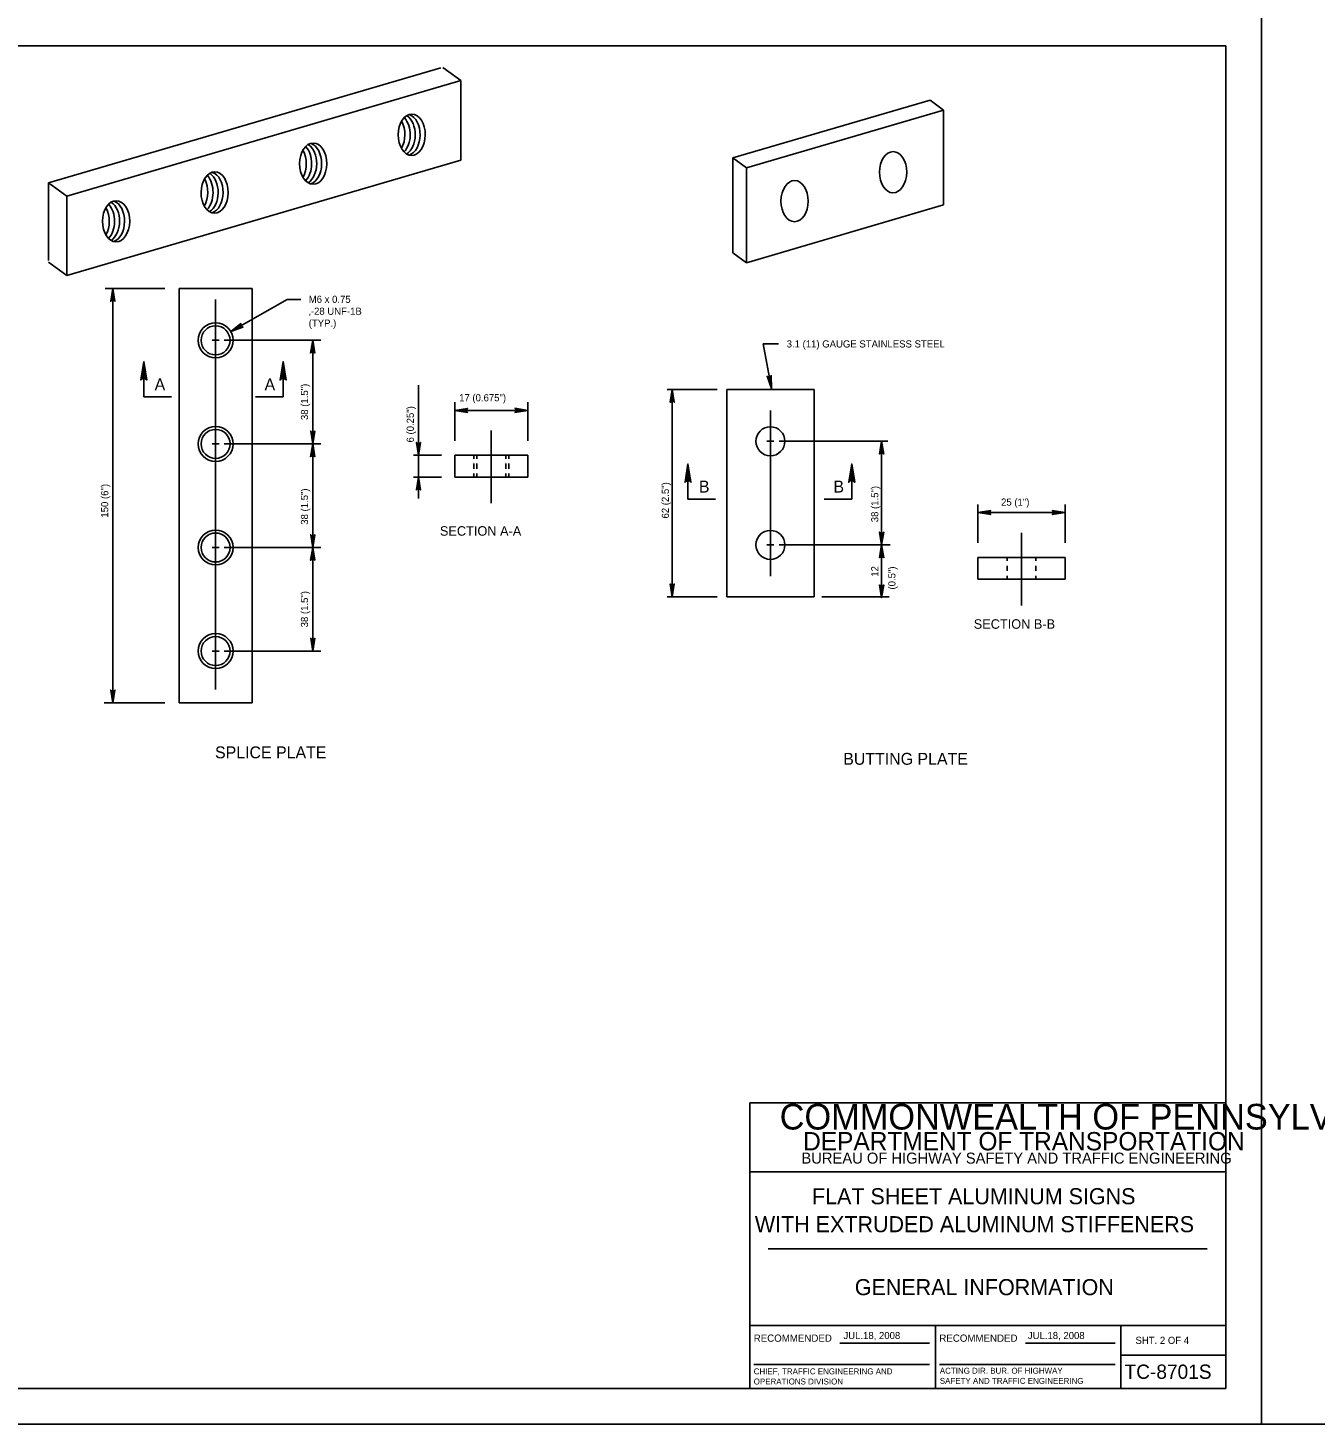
# Model space of a CAD drawing. Extents: x 650495 to 652241, y 298458 to 299646.
# Drawn here: x 650818 to 651359, y 298458 to 299044 of the extents above; entities that cross this region are included whole.
import ezdxf

# ---------------------------------------------------------------- set-up
doc = ezdxf.new("R2010")
doc.units = 0
for name, color, linetype in [('1', 7, 'Continuous'), ('2', 7, 'Continuous'), ('Default', 7, 'Continuous'), ('PLT-BNDY', 7, 'Continuous')]:
    doc.layers.add(name, color=color, linetype=linetype)

msp = doc.modelspace()

# ---------------------------------------------------------------- linework, layer by layer
at = {"layer": '1'}
for p, q in [((650535.31, 299036.63), (651321.31, 299036.63)), ((651321.31, 298472.63), (651321.31, 299036.63)), ((651121.31, 298472.63), (651121.31, 298592.63)), ((651121.31, 298592.63), (651321.31, 298592.63)), ((651321.31, 298563.63), (651121.31, 298563.63)), ((651129.06, 298531.31), (651313.56, 298531.31)), ((651121.31, 298499), (651321.31, 298499)), ((651199.31, 298499), (651199.31, 298472.63)), ((651277.19, 298472.63), (651277.19, 298499)), ((651159.24, 298491.57), (651196.87, 298491.57)), ((651237.24, 298491.57), (651274.87, 298491.57)), ((651122.99, 298482.68), (651196.87, 298482.68)), ((651200.99, 298482.68), (651274.87, 298482.68)), ((651277.19, 298486.63), (651321.31, 298486.63)), ((651321.31, 298472.63), (650535.31, 298472.63)), ((650535.31, 298472.63), (651121.31, 298472.63))]:
    msp.add_line(p, q, dxfattribs=at)
at = {"layer": '2'}
for p, q in [((650826.67, 298979.09), (650991.56, 299027.33)), ((650992.3, 299027.55), (650999.99, 299021.97)), ((650834.39, 298973.52), (650999.99, 299021.97)), ((650999.99, 298988.58), (650999.99, 299021.97)), ((651114.2, 298989.49), (651197.08, 299013.73)), ((651119.92, 298985.41), (651202.72, 299009.64)), ((651197.08, 299013.73), (651202.72, 299009.64)), ((651202.72, 298969.74), (651202.72, 299009.64)), ((650834.39, 298940.12), (650999.99, 298988.58)), ((651114.2, 298989.56), (651119.92, 298985.41)), ((651114.2, 298949.66), (651114.2, 298989.56)), ((651119.92, 298945.51), (651119.92, 298985.41)), ((650826.67, 298946.44), (650826.67, 298979.09)), ((650826.69, 298979.09), (650834.39, 298973.52)), ((650834.39, 298940.12), (650834.39, 298973.52)), ((651119.92, 298945.51), (651202.72, 298969.74)), ((650826.67, 298945.72), (650834.39, 298940.12)), ((651114.2, 298949.66), (651119.92, 298945.51)), ((650850.56, 298934.65), (650875.54, 298934.65)), ((650853.71, 298760.59), (650853.71, 298934.65)), ((650881.57, 298934.65), (650912.22, 298934.65)), ((650881.57, 298760.59), (650881.57, 298934.65)), ((650912.22, 298760.59), (650912.22, 298934.65)), ((650896.9, 298766.22), (650896.9, 298930.04)), ((650926.97, 298930.1), (650903.27, 298916.54)), ((650926.97, 298930.1), (650932.73, 298930.1)), ((650895.38, 298912.89), (650898.35, 298912.89)), ((650900.54, 298912.89), (650941.08, 298912.89)), ((650937.69, 298869.38), (650937.69, 298912.89)), ((651126.94, 298911.46), (651133.46, 298911.46)), ((651126.94, 298911.46), (651130.47, 298892.65)), ((650866.76, 298889.13), (650866.76, 298903.94)), ((650925.24, 298889.13), (650925.24, 298903.94)), ((650982.14, 298864.61), (650982.14, 298894.09)), ((651086.58, 298892.22), (651107.57, 298892.22)), ((651088.75, 298805.19), (651088.75, 298892.22)), ((651111.68, 298805.19), (651111.68, 298892.22)), ((651111.68, 298892.22), (651148.32, 298892.22)), ((651148.32, 298805.19), (651148.32, 298892.22)), ((650866.76, 298889.13), (650878.34, 298889.13)), ((650925.24, 298889.13), (650913.65, 298889.13)), ((650997.4, 298870.71), (650997.4, 298886.88)), ((651028.05, 298870.71), (651028.05, 298886.88)), ((650997.4, 298883.47), (651028.05, 298883.47)), ((651130, 298813.85), (651130, 298883.44)), ((651012.73, 298844.49), (651012.73, 298875.01)), ((650895.38, 298869.38), (650898.35, 298869.38)), ((650900.54, 298869.38), (650941.08, 298869.38)), ((650937.69, 298825.86), (650937.69, 298869.38)), ((651128.48, 298870.47), (651131.45, 298870.47)), ((651133.64, 298870.47), (651179.4, 298870.47)), ((651176.75, 298826.95), (651176.75, 298870.47)), ((650980.02, 298864.61), (650991.76, 298864.61)), ((650982.14, 298855.45), (650982.14, 298864.61)), ((650997.4, 298864.61), (651028.05, 298864.61)), ((650997.4, 298855.45), (650997.4, 298864.61)), ((651005.38, 298863.17), (651005.38, 298864.61)), ((651006.64, 298863.17), (651006.64, 298864.61)), ((651018.81, 298863.17), (651018.81, 298864.61)), ((651020.07, 298863.17), (651020.07, 298864.61)), ((651028.05, 298855.45), (651028.05, 298864.61)), ((651005.38, 298858.96), (651005.38, 298861.15)), ((651006.64, 298858.96), (651006.64, 298861.15)), ((651018.81, 298858.96), (651018.81, 298861.15)), ((651020.07, 298858.96), (651020.07, 298861.15)), ((651095.37, 298846.19), (651095.37, 298860.99)), ((651164.18, 298846.19), (651164.18, 298860.99)), ((650980.02, 298855.45), (650991.76, 298855.45)), ((650982.14, 298846.51), (650982.14, 298855.45)), ((650997.4, 298855.45), (651028.05, 298855.45)), ((651005.38, 298855.45), (651005.38, 298856.89)), ((651006.64, 298855.45), (651006.64, 298856.89)), ((651018.81, 298855.45), (651018.81, 298856.89)), ((651020.07, 298855.45), (651020.07, 298856.89)), ((651095.37, 298846.19), (651106.96, 298846.19)), ((651164.18, 298846.19), (651152.59, 298846.19)), ((651217.18, 298827.77), (651217.18, 298843.93)), ((651217.18, 298840.53), (651253.82, 298840.53)), ((651253.82, 298827.77), (651253.82, 298843.93)), ((651235.5, 298801.54), (651235.5, 298832.07)), ((650895.38, 298825.86), (650898.35, 298825.86)), ((650900.54, 298825.86), (650941.08, 298825.86)), ((650937.69, 298782.35), (650937.69, 298825.86)), ((651128.48, 298826.95), (651131.45, 298826.95)), ((651133.64, 298826.95), (651180.3, 298826.95)), ((651176.75, 298804.74), (651176.75, 298826.95)), ((651217.18, 298821.67), (651253.82, 298821.67)), ((651217.18, 298812.51), (651217.18, 298821.67)), ((651229.42, 298820.23), (651229.42, 298821.67)), ((651229.42, 298816.02), (651229.42, 298818.21)), ((651241.59, 298820.23), (651241.59, 298821.67)), ((651241.59, 298816.02), (651241.59, 298818.21)), ((651253.82, 298812.51), (651253.82, 298821.67)), ((651217.18, 298812.51), (651253.82, 298812.51)), ((651229.42, 298812.51), (651229.42, 298813.95)), ((651241.59, 298812.51), (651241.59, 298813.95)), ((651086.58, 298805.19), (651107.57, 298805.19)), ((651111.68, 298805.19), (651148.32, 298805.19)), ((651179.85, 298805.19), (651151.63, 298805.19)), ((650895.38, 298782.35), (650898.35, 298782.35)), ((650900.54, 298782.35), (650941.08, 298782.35)), ((650850.12, 298760.59), (650875.54, 298760.59)), ((650881.57, 298760.59), (650912.22, 298760.59))]:
    msp.add_line(p, q, dxfattribs=at)
for points in [[(650853.07, 298929.54), (650853.44, 298929.73), (650853.71, 298934.65), (650853.07, 298929.54), (650852.84, 298929.28), (650853.71, 298934.65), (650853.95, 298929.74), (650854.32, 298929.56), (650853.71, 298934.65), (650854.56, 298929.28), (650854.32, 298929.56)], [(650908.02, 298918.52), (650907.67, 298918.75), (650903.27, 298916.54), (650908.02, 298918.52), (650908.36, 298918.45), (650903.27, 298916.54), (650907.41, 298919.19), (650907.39, 298919.6), (650903.27, 298916.54), (650907.51, 298919.95), (650907.39, 298919.6)], [(650937.05, 298907.78), (650937.42, 298907.97), (650937.69, 298912.89), (650937.05, 298907.78), (650936.83, 298907.52), (650937.69, 298912.89), (650937.94, 298907.98), (650938.3, 298907.8), (650937.69, 298912.89), (650938.55, 298907.52), (650938.3, 298907.8)], [(650865.84, 298896.58), (650866.37, 298896.85), (650866.76, 298903.94), (650865.84, 298896.58), (650865.51, 298896.2), (650866.76, 298903.94), (650867.11, 298896.86), (650867.64, 298896.6), (650866.76, 298903.94), (650867.99, 298896.2), (650867.64, 298896.6)], [(650926.16, 298896.58), (650925.63, 298896.85), (650925.24, 298903.94), (650926.16, 298896.58), (650926.49, 298896.2), (650925.24, 298903.94), (650924.89, 298896.86), (650924.36, 298896.6), (650925.24, 298903.94), (650924.01, 298896.2), (650924.36, 298896.6)], [(651130.16, 298897.78), (651129.83, 298897.53), (651130.47, 298892.65), (651130.16, 298897.78), (651130.33, 298898.08), (651130.47, 298892.65), (651129.32, 298897.43), (651128.93, 298897.54), (651130.47, 298892.65), (651128.64, 298897.77), (651128.93, 298897.54)], [(651088.11, 298887.11), (651088.48, 298887.3), (651088.75, 298892.22), (651088.11, 298887.11), (651087.89, 298886.85), (651088.75, 298892.22), (651088.99, 298887.31), (651089.36, 298887.13), (651088.75, 298892.22), (651089.61, 298886.85), (651089.36, 298887.13)], [(651002.51, 298882.83), (651002.32, 298883.2), (650997.4, 298883.47), (651002.51, 298882.83), (651002.77, 298882.6), (650997.4, 298883.47), (651002.32, 298883.71), (651002.5, 298884.08), (650997.4, 298883.47), (651002.77, 298884.32), (651002.5, 298884.08)], [(651022.94, 298884.11), (651023.13, 298883.74), (651028.05, 298883.47), (651022.94, 298884.11), (651022.68, 298884.33), (651028.05, 298883.47), (651023.14, 298883.23), (651022.96, 298882.86), (651028.05, 298883.47), (651022.68, 298882.62), (651022.96, 298882.86)], [(650938.33, 298874.49), (650937.97, 298874.3), (650937.69, 298869.38), (650938.33, 298874.49), (650938.56, 298874.75), (650937.69, 298869.38), (650937.45, 298874.29), (650937.08, 298874.47), (650937.69, 298869.38), (650936.84, 298874.75), (650937.08, 298874.47)], [(650937.05, 298864.27), (650937.42, 298864.46), (650937.69, 298869.38), (650937.05, 298864.27), (650936.83, 298864.01), (650937.69, 298869.38), (650937.94, 298864.46), (650938.3, 298864.28), (650937.69, 298869.38), (650938.55, 298864.01), (650938.3, 298864.28)], [(650982.78, 298869.72), (650982.41, 298869.53), (650982.14, 298864.61), (650982.78, 298869.72), (650983.01, 298869.98), (650982.14, 298864.61), (650981.9, 298869.53), (650981.53, 298869.71), (650982.14, 298864.61), (650981.29, 298869.98), (650981.53, 298869.71)], [(651176.11, 298865.36), (651176.48, 298865.55), (651176.75, 298870.47), (651176.11, 298865.36), (651175.88, 298865.1), (651176.75, 298870.47), (651176.99, 298865.55), (651177.36, 298865.37), (651176.75, 298870.47), (651177.6, 298865.1), (651177.36, 298865.37)], [(651094.45, 298853.64), (651094.98, 298853.91), (651095.37, 298860.99), (651094.45, 298853.64), (651094.12, 298853.26), (651095.37, 298860.99), (651095.72, 298853.92), (651096.25, 298853.66), (651095.37, 298860.99), (651096.6, 298853.26), (651096.25, 298853.66)], [(651165.1, 298853.64), (651164.57, 298853.91), (651164.18, 298860.99), (651165.1, 298853.64), (651165.42, 298853.26), (651164.18, 298860.99), (651163.83, 298853.92), (651163.3, 298853.66), (651164.18, 298860.99), (651162.95, 298853.26), (651163.3, 298853.66)], [(650981.5, 298850.34), (650981.87, 298850.53), (650982.14, 298855.45), (650981.5, 298850.34), (650981.27, 298850.08), (650982.14, 298855.45), (650982.38, 298850.54), (650982.75, 298850.36), (650982.14, 298855.45), (650982.99, 298850.08), (650982.75, 298850.36)], [(651222.29, 298839.88), (651222.1, 298840.25), (651217.18, 298840.53), (651222.29, 298839.88), (651222.55, 298839.66), (651217.18, 298840.53), (651222.09, 298840.77), (651222.27, 298841.14), (651217.18, 298840.53), (651222.55, 298841.38), (651222.27, 298841.14)], [(651248.72, 298841.17), (651248.91, 298840.8), (651253.82, 298840.53), (651248.72, 298841.17), (651248.45, 298841.39), (651253.82, 298840.53), (651248.91, 298840.28), (651248.73, 298839.92), (651253.82, 298840.53), (651248.45, 298839.67), (651248.73, 298839.92)], [(650938.33, 298830.97), (650937.97, 298830.78), (650937.69, 298825.86), (650938.33, 298830.97), (650938.56, 298831.23), (650937.69, 298825.86), (650937.45, 298830.78), (650937.08, 298830.96), (650937.69, 298825.86), (650936.84, 298831.23), (650937.08, 298830.96)], [(651177.39, 298832.06), (651177.02, 298831.87), (651176.75, 298826.95), (651177.39, 298832.06), (651177.61, 298832.32), (651176.75, 298826.95), (651176.5, 298831.86), (651176.14, 298832.04), (651176.75, 298826.95), (651175.89, 298832.32), (651176.14, 298832.04)], [(650937.05, 298820.75), (650937.42, 298820.94), (650937.69, 298825.86), (650937.05, 298820.75), (650936.83, 298820.49), (650937.69, 298825.86), (650937.94, 298820.95), (650938.3, 298820.77), (650937.69, 298825.86), (650938.55, 298820.49), (650938.3, 298820.77)], [(651176.11, 298821.84), (651176.48, 298822.03), (651176.75, 298826.95), (651176.11, 298821.84), (651175.88, 298821.58), (651176.75, 298826.95), (651176.99, 298822.04), (651177.36, 298821.86), (651176.75, 298826.95), (651177.6, 298821.58), (651177.36, 298821.86)], [(651089.39, 298810.3), (651089.02, 298810.11), (651088.75, 298805.19), (651089.39, 298810.3), (651089.62, 298810.56), (651088.75, 298805.19), (651088.51, 298810.11), (651088.14, 298810.29), (651088.75, 298805.19), (651087.9, 298810.56), (651088.14, 298810.29)], [(651177.39, 298809.85), (651177.02, 298809.66), (651176.75, 298804.74), (651177.39, 298809.85), (651177.61, 298810.11), (651176.75, 298804.74), (651176.5, 298809.66), (651176.14, 298809.84), (651176.75, 298804.74), (651175.89, 298810.11), (651176.14, 298809.84)], [(650938.33, 298787.46), (650937.97, 298787.27), (650937.69, 298782.35), (650938.33, 298787.46), (650938.56, 298787.72), (650937.69, 298782.35), (650937.45, 298787.26), (650937.08, 298787.44), (650937.69, 298782.35), (650936.84, 298787.72), (650937.08, 298787.44)], [(650854.35, 298765.7), (650853.98, 298765.51), (650853.71, 298760.59), (650854.35, 298765.7), (650854.57, 298765.96), (650853.71, 298760.59), (650853.46, 298765.5), (650853.1, 298765.68), (650853.71, 298760.59), (650852.85, 298765.96), (650853.1, 298765.68)]]:
    msp.add_lwpolyline(points, dxfattribs=at)
for centre, radius in [((650896.9, 298912.89), 7.34), ((650896.9, 298912.89), 6.09), ((650896.9, 298869.38), 7.34), ((650896.9, 298869.38), 6.09), ((651130, 298870.47), 6.09), ((650896.9, 298825.86), 7.34), ((650896.9, 298825.86), 6.09), ((651130, 298826.95), 6.09), ((650896.9, 298782.35), 7.34), ((650896.9, 298782.35), 6.09)]:
    msp.add_circle(centre, radius, dxfattribs=at)
for centre in [(650979.29, 298999.22), (650937.89, 298987.11), (651181.56, 298983.5), (650896.49, 298974.99), (651140.16, 298971.38), (650855.09, 298962.88)]:
    msp.add_ellipse(centre, major_axis=(0.05, 8.67), ratio=0.658454, dxfattribs=at)
for centre, start_param, end_param in [((650970.71, 298999.22), 4.009549, 5.408338), ((650972.93, 298999.22), 3.741593, 5.67105), ((650975.05, 298999.22), 3.535802, 5.876738), ((650977.12, 298999.22), 3.354344, 6.055413), ((650929.3, 298987.11), 4.009549, 5.408338), ((650931.53, 298987.11), 3.741593, 5.67105), ((650933.65, 298987.11), 3.535802, 5.876738), ((650935.72, 298987.11), 3.354344, 6.055413), ((650887.9, 298974.99), 4.009549, 5.408338), ((650890.12, 298974.99), 3.741593, 5.67105), ((650892.25, 298974.99), 3.535802, 5.876738), ((650894.32, 298974.99), 3.354344, 6.055413), ((650846.5, 298962.88), 4.009549, 5.408338), ((650848.72, 298962.88), 3.741593, 5.67105), ((650850.84, 298962.88), 3.535802, 5.876738), ((650852.92, 298962.88), 3.354344, 6.055413)]:
    msp.add_ellipse(centre, major_axis=(0.05, 8.67), ratio=0.658454, start_param=start_param, end_param=end_param, dxfattribs=at)
at = {"layer": 'PLT-BNDY'}
for points in [[(650495.31, 299051.63), (651336.31, 299051.63), (651336.31, 298457.63), (650495.31, 298457.63)], [(651336.31, 299051.63), (652177.31, 299051.63), (652177.31, 298457.63), (651336.31, 298457.63)]]:
    msp.add_lwpolyline(points, close=True, dxfattribs=at)

# ---------------------------------------------------------------- texts
at = {"layer": '1'}
for s, height, p in [('COMMONWEALTH OF PENNSYLVANIA', 10.7828, (651133.9, 298581.36)), ('DEPARTMENT OF TRANSPORTATION', 7.6837, (651143.76, 298572.61)), ('BUREAU OF HIGHWAY SAFETY AND TRAFFIC ENGINEERING', 4.6253, (651143.04, 298567.04)), ('FLAT SHEET ALUMINUM SIGNS', 6.75, (651147.47, 298549.97)), ('WITH EXTRUDED ALUMINUM STIFFENERS', 6.75, (651123.47, 298538.22)), ('GENERAL INFORMATION', 6.75, (651165.45, 298511.78)), ('RECOMMENDED', 3.048, (651122.99, 298492.2)), ('RECOMMENDED', 3.048, (651200.99, 298492.2)), ('SHT. 2 OF 4', 3, (651283.4, 298491.31)), ('TC-8701S', 6, (651278.79, 298476.63)), ('OPERATIONS DIVISION', 2.5, (651122.99, 298474.26)), ('CHIEF, TRAFFIC ENGINEERING AND', 2.5, (651122.99, 298478.51))]:
    msp.add_text(s, height=height, dxfattribs=at).set_placement(p)
at = {"layer": '2'}
for s, height, p in [('M6 x 0.75', 3, (650936.02, 298928.62)), ('‚-28 UNF-1B', 3, (650936.02, 298923.62)), ('(TYP.)', 3, (650936.02, 298918.62)), ('3.1 (11) GAUGE STAINLESS STEEL', 3, (651136.84, 298909.88)), ('A', 5, (650917.46, 298891.9)), ('17 (0.675")', 3, (650999.22, 298887.28)), ('B', 5, (651099.96, 298848.95)), ('B', 5, (651156.48, 298848.95)), ('25 (1")', 3, (651226.93, 298843.44)), ('SECTION A-A', 4, (650991.15, 298830.81)), ('SECTION B-B', 4, (651215.44, 298791.72)), ('SPLICE PLATE', 5, (650896.65, 298737.3)), ('BUTTING PLATE', 5, (651160.6, 298734.59)), ('JUL.18, 2008', 3, (651160.69, 298493.34))]:
    msp.add_text(s, height=height, dxfattribs=at).set_placement(p)
for s, height, rotation, p in [('A', 5, 360, (650871.27, 298891.9)), ('38 (1.5")', 3, 90, (650935.74, 298879.41)), ('6 (0.25")', 3, 90, (650980.19, 298869.99)), ('150 (6")', 3, 90, (650851.79, 298838.42)), ('62 (2.5")', 3, 90, (651087.36, 298838.04)), ('38 (1.5")', 3, 90, (651175.35, 298836.47)), ('38 (1.5")', 3, 90, (650935.74, 298835.42)), ('12', 3, 90, (651175.35, 298813.59)), ('(0.5")', 3, 90, (651182.54, 298808.21)), ('38 (1.5")', 3, 90, (650935.74, 298792.32)), ('JUL.18, 2008', 3, 360, (651238.17, 298493.34))]:
    msp.add_text(s, height=height, rotation=rotation, dxfattribs=at).set_placement(p)
at = {"layer": 'Default'}
for s, p in [('ACTING DIR. BUR. OF HIGHWAY', (651201.18, 298478.78)), ('SAFETY AND TRAFFIC ENGINEERING', (651201.18, 298474.53))]:
    msp.add_text(s, height=2.5, dxfattribs=at).set_placement(p)

doc.saveas('drawing.dxf')
